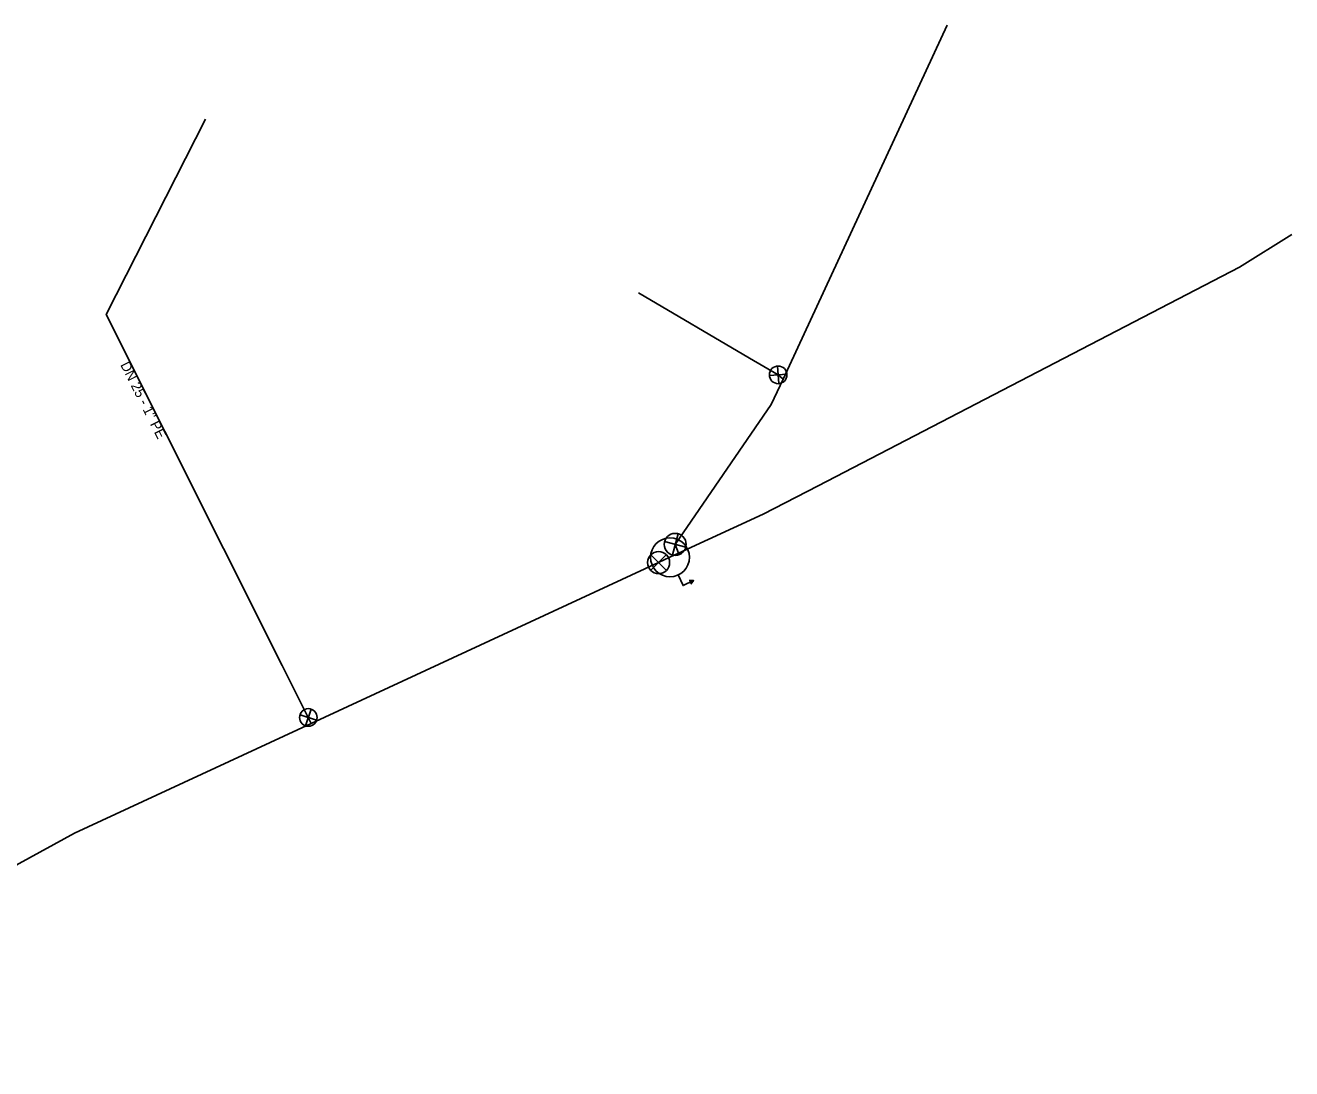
# Model space of a CAD drawing. Extents: x -483822 to -483707, y -1128589 to -1128518.
# Drawn here: x -483764.7 to -483707.2, y -1128565.7 to -1128518.3 of the extents above; entities that cross this region are included whole.
import ezdxf

# ---------------------------------------------------------------- set-up
doc = ezdxf.new("R2010")
doc.units = 0
for name, color, linetype in [('_pripojka_prevzato_z_dokumentace_', 7, 'Continuous'), ('_pripojka_priblizne_', 7, 'Continuous'), ('_voda_smvak_prevzato_z_dokumentace_', 7, 'Continuous'), ('Default', 7, 'Continuous'), ('MoLevel 27', 7, 'Continuous'), ('MoLevel 28', 7, 'Continuous'), ('MoLevel 32', 7, 'Continuous'), ('MoLevel 53', 7, 'Continuous')]:
    doc.layers.add(name, color=color, linetype=linetype)

# ---------------------------------------------------------------- blocks, each defined once
blk = doc.blocks.new('_uzaver_')
at = {"layer": 'Default'}
for p, q in [((-0.000035, -0.000035), (0.000035, 0.000035)), ((0.000035, -0.000035), (-0.000035, 0.000035))]:
    blk.add_line(p, q, dxfattribs=at)
for radius in [0.00005, 0.0000025]:
    blk.add_circle((0, 0), radius, dxfattribs=at)
blk = doc.blocks.new('_uzaver_pripojka_')
at = {"layer": 'Default'}
for p, q in [((-0.000035, -0.000035), (0.000035, 0.000035)), ((0.000035, -0.000035), (-0.000035, 0.000035))]:
    blk.add_line(p, q, dxfattribs=at)
for radius in [0.00005, 0.0000025]:
    blk.add_circle((0, 0), radius, dxfattribs=at)
blk = doc.blocks.new('_hydrant_voda_')
at = {"layer": 'Default'}
blk.add_line((0.00003, -0.00008), (0.00002, -0.000085), dxfattribs=at)
blk.add_lwpolyline([(0, -0.00005), (0, -0.00008), (0.00003, -0.00008), (0.00002, -0.000075)], dxfattribs=at)
blk.add_circle((0, 0), 0.00005, dxfattribs=at)

msp = doc.modelspace()

# ---------------------------------------------------------------- linework, layer by layer
at = {"layer": '_pripojka_prevzato_z_dokumentace_'}
for p, q in [((-483736.851, -1128530.479), (-483731.809, -1128533.433)), ((-483751.819, -1128549.73), (-483751.684, -1128549.998))]:
    msp.add_line(p, q, dxfattribs=at)
msp.add_lwpolyline([(-483731.809, -1128533.433), (-483730.51, -1128534.194), (-483730.288, -1128534.388)], dxfattribs=at)
at = {"layer": '_pripojka_priblizne_'}
msp.add_line((-483753.004, -1128547.368), (-483751.819, -1128549.73), dxfattribs=at)
msp.add_lwpolyline([(-483756.486, -1128522.6), (-483760.99, -1128531.454), (-483753.004, -1128547.368)], dxfattribs=at)
at = {"layer": '_voda_smvak_prevzato_z_dokumentace_'}
for p, q in [((-483735.18, -1128541.883), (-483735.027, -1128542.286)), ((-483735.417, -1128542.466), (-483735.932, -1128542.704)), ((-483735.027, -1128542.286), (-483735.417, -1128542.466))]:
    msp.add_line(p, q, dxfattribs=at)
for points in [[(-483722.845, -1128518.344), (-483730.288, -1128534.388), (-483730.823, -1128535.541), (-483735.18, -1128541.883)], [(-483707.22, -1128527.824), (-483709.592, -1128529.316), (-483728.701, -1128539.219), (-483731.188, -1128540.508), (-483735.027, -1128542.286)], [(-483735.932, -1128542.704), (-483751.684, -1128549.998), (-483762.419, -1128554.968), (-483772.473, -1128560.474), (-483781.93, -1128565.654), (-483797.478, -1128565.654), (-483809.647, -1128550.046), (-483811.894, -1128547.165)]]:
    msp.add_lwpolyline(points, dxfattribs=at)

# ---------------------------------------------------------------- block references
at = {"layer": 'MoLevel 27', "xscale": 10000, "yscale": 10000, "rotation": 119.98245833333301}
msp.add_blockref('_uzaver_', (-483735.18, -1128541.883), dxfattribs=at)
at = {"layer": 'MoLevel 27', "xscale": 10000, "yscale": 10000}
msp.add_blockref('_uzaver_', (-483735.932, -1128542.704), dxfattribs=at)
at = {"layer": 'MoLevel 28', "xscale": 17636.68430335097, "yscale": 17636.68430335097, "rotation": 24.8449467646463}
msp.add_blockref('_hydrant_voda_', (-483735.417, -1128542.466), dxfattribs=at)
at = {"layer": 'MoLevel 53', "yscale": 7999.999999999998}
for p, xscale, rotation in [((-483730.509, -1128534.194), 8000.000000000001, -41.173866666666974), ((-483751.818, -1128549.729), 7999.999999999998, 116.649172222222)]:
    msp.add_blockref('_uzaver_pripojka_', p, dxfattribs=dict(at, xscale=xscale, rotation=rotation))

# ---------------------------------------------------------------- texts
at = {"layer": 'MoLevel 32'}
msp.add_text("DN 25 - 1'' PE", height=0.455, rotation=296.64776, dxfattribs=at).set_placement((-483760.356, -1128533.733))

doc.saveas('drawing.dxf')
